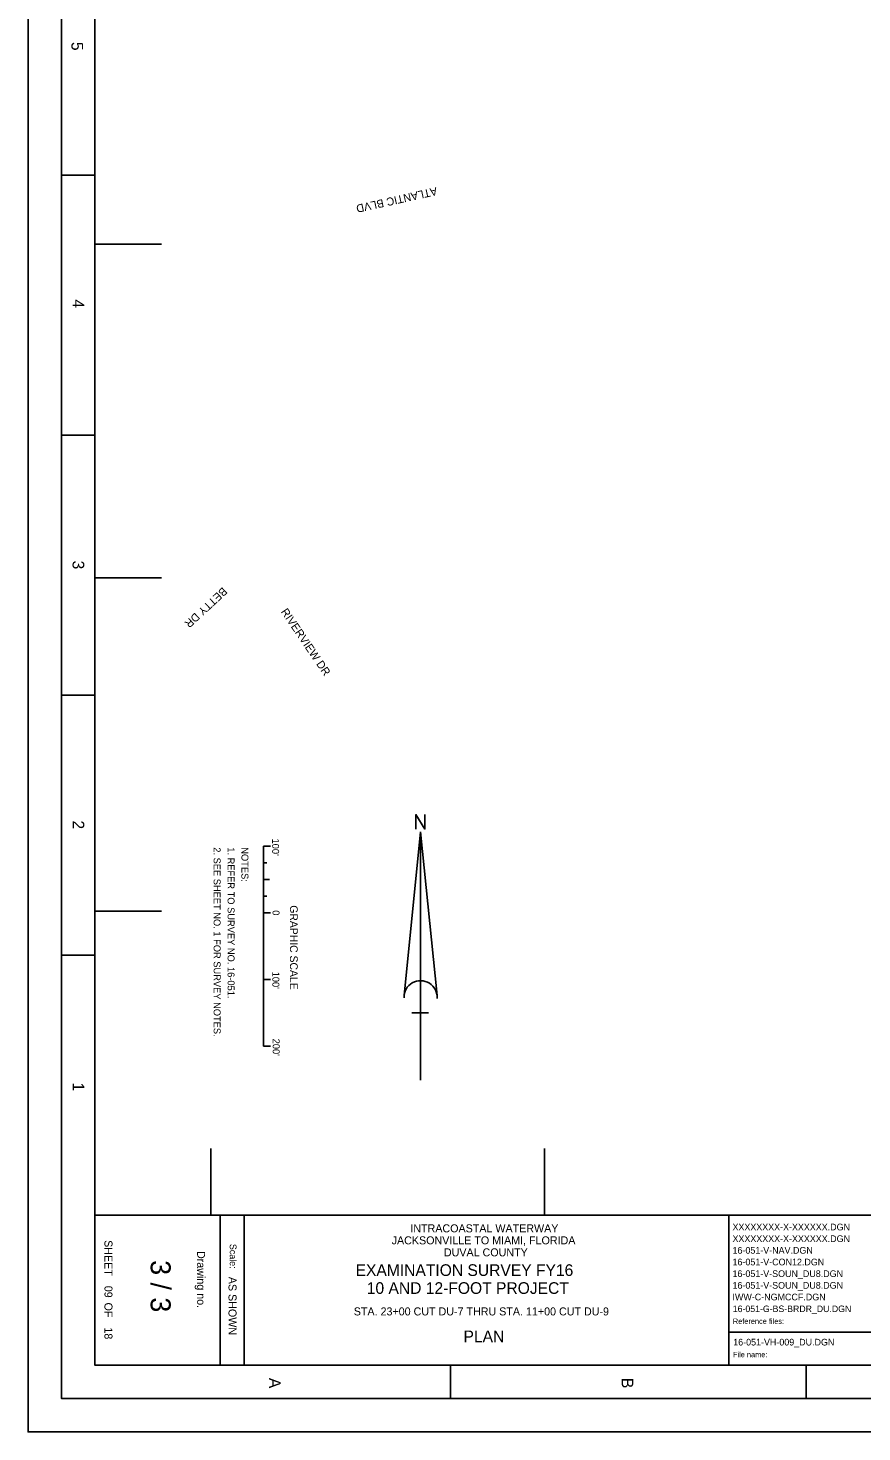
# Model space of a CAD drawing. Extents: x 516226 to 519626, y 2175719 to 2180119.
# Drawn here: x 516226 to 517476, y 2175719 to 2177824 of the extents above; entities that cross this region are included whole.
import ezdxf

# ---------------------------------------------------------------- set-up
doc = ezdxf.new("R2010")
doc.units = 0
for name, color, linetype in [('G-ANNO-NPLT', 7, 'Continuous'), ('G-ANNO-TEXT-DRWG', 7, 'Continuous'), ('G-ANNO-TEXT-PROJ', 7, 'Continuous'), ('G-ANNO-TEXT-TTLB', 7, 'Continuous'), ('G-ANNO-TTLB', 7, 'Continuous'), ('V-ANNO-NOTE', 7, 'Continuous'), ('V-ANNO-SYMB', 7, 'Continuous'), ('V-ROAD-IDEN', 7, 'Continuous'), ('V-TOPO-COOR-STAT', 7, 'Continuous')]:
    doc.layers.add(name, color=color, linetype=linetype)

msp = doc.modelspace()

# ---------------------------------------------------------------- linework, layer by layer
at = {"layer": 'G-ANNO-NPLT'}
msp.add_lwpolyline([(519626, 2180118.8), (519626, 2175718.8), (516226, 2175718.8), (516226, 2180118.8)], close=True, dxfattribs=at)
msp.add_lwpolyline([(516276, 2175718.6), (516226, 2175718.6), (516226, 2175768.6)], dxfattribs=at)
at = {"layer": 'G-ANNO-TTLB'}
for p, q in [((516276, 2177603.8), (516326, 2177603.8)), ((516276, 2177213.8), (516326, 2177213.8)), ((516276, 2176823.8), (516326, 2176823.8)), ((516276, 2176433.8), (516326, 2176433.8)), ((519526, 2176043.8), (516326, 2176043.8)), ((516514.1, 2176043.8), (516514.1, 2175818.8)), ((516549.8, 2176043.8), (516549.8, 2175818.8)), ((517276.8, 2176043.8), (517276.8, 2175818.8)), ((517628.1, 2175868.1), (517276.8, 2175868.1)), ((516859.3, 2175768.8), (516859.3, 2175818.8)), ((517392.6, 2175768.8), (517392.6, 2175818.8))]:
    msp.add_line(p, q, dxfattribs=at)
for points in [[(516276, 2180068.8), (516276, 2175768.8), (519576, 2175768.8), (519576, 2180068.8)], [(519526, 2175818.8), (519526, 2179943.8), (516326, 2179943.8), (516326, 2175818.8)]]:
    msp.add_lwpolyline(points, close=True, dxfattribs=at)
at = {"layer": 'V-ANNO-NOTE'}
for p, q in [((516579.1, 2176597.4), (516579.1, 2176297.4)), ((516579.1, 2176597.4), (516589.6, 2176597.4)), ((516579.1, 2176572.4), (516583.9, 2176572.4)), ((516579.1, 2176547.4), (516587.7, 2176547.4)), ((516579.1, 2176522.4), (516583.9, 2176522.4)), ((516579.1, 2176497.4), (516589.6, 2176497.4)), ((516579.1, 2176497.4), (516584.1, 2176497.4)), ((516579.1, 2176497.4), (516589.6, 2176497.4)), ((516579.1, 2176397.4), (516589.6, 2176397.4)), ((516579.1, 2176297.4), (516589.6, 2176297.4))]:
    msp.add_line(p, q, dxfattribs=at)
at = {"layer": 'V-ANNO-SYMB'}
for p, q in [((516789.7, 2176373.1), (516814.4, 2176618.9)), ((516814.4, 2176246.5), (516814.4, 2176618.9)), ((516839.1, 2176373.1), (516814.4, 2176618.9)), ((516826.1, 2176347.1), (516801.3, 2176347.1))]:
    msp.add_line(p, q, dxfattribs=at)
msp.add_lwpolyline([(516807.5, 2176622.9), (516807.5, 2176644.6), (516821, 2176622.9), (516821, 2176644.6)], dxfattribs=at)
msp.add_arc((516814.4, 2176370.7), 24.8, 355.2984, 182.0673, dxfattribs=at)
at = {"layer": 'V-TOPO-COOR-STAT'}
for p, q in [((516426, 2177500), (516326, 2177500)), ((516426, 2177000), (516326, 2177000)), ((516426, 2176500), (516326, 2176500)), ((516500, 2176043.8), (516500, 2176143.8)), ((517000, 2176043.8), (517000, 2176143.8))]:
    msp.add_line(p, q, dxfattribs=at)

# ---------------------------------------------------------------- texts
at = {"layer": 'G-ANNO-TEXT-DRWG'}
for s, height, rotation, p in [('XXXXXXXX-X-XXXXXX.DGN', 10, 360, (517282.1, 2176021)), ('XXXXXXXX-X-XXXXXX.DGN', 10, 360, (517282.1, 2176003.5)), ('16-051-V-NAV.DGN', 10, 360, (517282.1, 2175986)), ('3 / 3', 30, 270, (516409.8, 2175976.2)), ('16-051-V-CON12.DGN', 10, 360, (517282.1, 2175968.5)), ('16-051-V-SOUN_DU8.DGN', 10, 360, (517282.1, 2175951)), (' 09          18', 12, 270, (516340.5, 2175942.3)), ('16-051-V-SOUN_DU8.DGN', 10, 360, (517282.1, 2175933.5)), ('IWW-C-NGMCCF.DGN', 10, 360, (517282.1, 2175916)), ('STA. 23+00 CUT DU-7 THRU STA. 11+00 CUT DU-9', 12, 360, (516714.3, 2175893.4)), ('PLAN', 17.5, 360, (516878.8, 2175853.2)), ('16-051-VH-009_DU.DGN', 10, 360, (517283.2, 2175848.3))]:
    msp.add_text(s, height=height, rotation=rotation, dxfattribs=at).set_placement(p)
at = {"layer": 'G-ANNO-TEXT-PROJ'}
for s, height, p in [('INTRACOASTAL WATERWAY', 12, (516799.1, 2176018)), ('JACKSONVILLE TO MIAMI, FLORIDA', 12, (516771.1, 2176000)), ('DUVAL COUNTY', 12, (516849.4, 2175982)), ('EXAMINATION SURVEY FY16', 17.5, (516717, 2175952.6)), ('10 AND 12-FOOT PROJECT', 17.5, (516733.8, 2175925.7)), ('16-051-G-BS-BRDR_DU.DGN', 9.8, (517282.5, 2175898.4))]:
    msp.add_text(s, height=height, rotation=360, dxfattribs=at).set_placement(p)
at = {"layer": 'G-ANNO-TEXT-TTLB'}
for s, height, rotation, p in [('SHEET         OF', 12, 270, (516340.5, 2176006.3)), ('Scale:', 10, 270, (516528.4, 2176000.7)), ('Drawing no.', 12, 270, (516479.4, 2175990)), ('AS SHOWN', 12, 270, (516526.5, 2175951.3)), ('Reference files:', 8, 360, (517282.6, 2175880.7)), ('File name:', 8, 360, (517282.8, 2175830.7))]:
    msp.add_text(s, height=height, rotation=rotation, dxfattribs=at).set_placement(p)
at = {"layer": 'G-ANNO-TTLB'}
for s, p in [('5', (516291, 2177803.6)), ('4', (516292.7, 2177417.4)), ('3', (516292.7, 2177025.6)), ('2', (516292.7, 2176635.8)), ('1', (516292.7, 2176242.7)), ('A', (516587.2, 2175799.7)), ('B', (517115.9, 2175799.7))]:
    msp.add_text(s, height=17.5, rotation=270, dxfattribs=at).set_placement(p)
at = {"layer": 'V-ANNO-NOTE'}
for s, height, p in [("100'", 10.42, (516591.9, 2176608.7)), ('2. SEE SHEET NO. 1 FOR SURVEY NOTES.', 10.416, (516504.2, 2176595.6)), ('1. REFER TO SURVEY NO. 16-051.', 10.416, (516525.1, 2176595.6)), ('NOTES:', 10.42, (516545.9, 2176595.6)), ('GRAPHIC SCALE', 11.666, (516618.6, 2176508.6)), ('0', 10.4, (516592.5, 2176501.1)), ("100'", 10.42, (516592.3, 2176409)), ("200'", 10.42, (516592.8, 2176308.5))]:
    msp.add_text(s, height=height, rotation=270, dxfattribs=at).set_placement(p)
at = {"layer": 'V-ROAD-IDEN'}
for s, rotation, p in [('ATLANTIC BLVD', 192.5925, (516837.9, 2177585.9)), ('BETTY DR', 222.9288, (516517.7, 2176986.5)), ('RIVERVIEW DR', 304.0628, (516604.4, 2176948.9))]:
    msp.add_text(s, height=12, rotation=rotation, dxfattribs=at).set_placement(p)

doc.saveas('drawing.dxf')
